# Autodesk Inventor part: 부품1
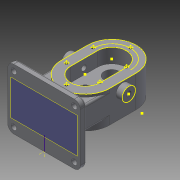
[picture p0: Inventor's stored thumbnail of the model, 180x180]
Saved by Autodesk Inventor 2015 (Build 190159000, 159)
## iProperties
Created: 2020-09
Part Number: 부품1
Material: 일반
Document SubType Name: Modeling
Designer: Main
Density: 1 g/cm^3
Appearance: 기본값
Author: Main
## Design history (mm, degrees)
sketch "스케치2"
  geometry: L1 (0, 0)-(0, -44); L2 (-40, 0)-(-40, -44); L3 (40, -44)-(40, 0); L4 (0, 0)-(0, -44); L5 (-24, 0)-(-24, -44); L6 (24, -44)-(24, 0); L7 (0, 0)-(0, -44); L8 (-31, 0)-(-31, -44); L9 (31, -44)-(31, 0); C1 r 12.5 at (0, 0); C2 r 12.5 at (0, -44); A1 r 40 centre (0, 0) between (40, 0) and (-40, 0); A2 r 40 centre (0, -44) between (-40, -44) and (40, -44); A3 r 24 centre (0, 0) between (24, 0) and (-24, 0); A4 r 24 centre (0, -44) between (-24, -44) and (24, -44); A5 r 31 centre (0, 0) between (31, 0) and (-31, 0); A6 r 31 centre (0, -44) between (-31, -44) and (31, -44); 3 further points
  constraints: 24 end point, 12 point on circle, 12 tangent, 8 centre point, 5 equal length, 3 midpoint, 2 coincident, 1 vertical
extrude "돌출1" new body sketch "스케치2" distance "d2" = 29; taper "d3" = 0 deg
extrude "돌출2" join sketch "스케치2" distance "d4" = 53; taper "d5" = 0 deg
extrude "돌출3" join sketch "스케치2" distance "d6" = 14; taper "d7" = 0 deg
sketch "스케치3"
  geometry: L1 (24, 0)-(24, -44) reference; L2 (-24, -44)-(-24, 0) reference; L3 (-40, 0)-(-40, -44) reference; L4 (40, -44)-(40, 0) reference; L5 (24, 0)-(24, -44) reference; L6 (-24, -44)-(-24, 0) reference; L7 (-40, 0)-(-40, -44) reference; L8 (40, -44)-(40, 0) reference; A1 r 24 centre (0, 0) between (24, 0) and (-24, 0) reference; A2 r 24 centre (0, -44) between (-24, -44) and (24, -44) reference; A3 r 40 centre (0, -44) between (-40, -44) and (40, -44) reference; A4 r 40 centre (0, 0) between (40, 0) and (-40, 0) reference; A5 r 31 centre (0, 0) between (31, 0) and (-31, 0) reference; A6 r 24 centre (0, 0) between (24, 0) and (-24, 0) reference; A7 r 24 centre (0, -44) between (-24, -44) and (24, -44) reference; A8 r 40 centre (0, -44) between (-40, -44) and (40, -44) reference; A9 r 40 centre (0, 0) between (40, 0) and (-40, 0) reference
  node "투영된 루프1"
node "작업 평면1"
sketch "스케치4"
  geometry: L1 (0, 53)-(-44, 53) reference; L2 (-22, 53)-(-22, 39); C1 r 11 at (-22, 39); 1 further point
  constraints: 2 end point, 1 centre point, 1 coincident, 1 midpoint, 1 vertical
extrude "돌출4" join sketch "스케치4" distance "d9" = 10; taper "d10" = 0 deg
sketch "스케치5"
  geometry: C1 r 11 at (0, 0) reference; 1 further point
hole "구멍1" diameter "d13" = 8.376; stored, may be unused: countersink angle "d17" = 90 deg, drill point angle "d19" = 118 deg; dims "d11" = 10, "d12" = 10, "d14" = 20, "d15" = 4, "d16" = 2, "d18" = 27.3
node "작업 평면2"
sketch "스케치6"
  geometry: L1 (-40, 0)-(-40, 53) reference; L2 (-40, 26.5)-(40, 26.5); L3 (40, 0)-(40, 53) reference; L4 (-60, 76.5)-(60, 76.5); L5 (60, 76.5)-(60, -23.5); L6 (60, -23.5)-(-60, -23.5); L7 (-60, -23.5)-(-60, 76.5); L8 (-60, 76.5)-(60, -23.5); L9 (60, 76.5)-(-60, -23.5); 2 further points
  constraints: 14 end point, 5 midpoint, 2 parallel, 1 horizontal, 1 perpendicular
extrude "돌출5" join sketch "스케치6" distance "d21" = 10; taper "d22" = 0 deg
fillet "모깎기1" dims "d23" = 10
sketch "스케치7"
  geometry: C1 r 4.5 at (-50, 13.5); C2 r 4.5 at (50, 13.5); C3 r 4.5 at (50, -66.5); C4 r 4.5 at (-50, -66.5); A1 r 10 centre (50, 13.5) between (60, 13.5) and (50, 23.5) reference; A2 r 10 centre (-50, 13.5) between (-50, 23.5) and (-60, 13.5) reference; A3 r 10 centre (-50, -66.5) between (-60, -66.5) and (-50, -76.5) reference; A4 r 10 centre (50, -66.5) between (50, -76.5) and (60, -66.5) reference; 1 further point
  constraints: 4 centre point, 4 coincident
extrude "돌출6" cut sketch "스케치7" distance "d24" = 10; taper "d25" = 0 deg
sketch "스케치8"
  geometry: 1 further point
sketch "스케치9"
  geometry: L1 (-112, -23.5)-(-112, 0); 1 further point
  constraints: 2 end point, 1 vertical
node "작업 평면3"
sketch "스케치10"
  geometry: L1 (0, -102)-(-40, -102); L2 (50, -102)-(-50, -102) reference; L3 (-40, -102)-(-40, -44); L4 (-40, 0)-(-40, -44) reference; L5 (0, -102)-(40, -102); L6 (40, -102)-(40, -44); A1 r 40 centre (0, -44) between (-40, -44) and (40, -44) reference; A2 r 40 centre (0, -44) between (-40, -44) and (40, -44); 1 further point
  constraints: 8 end point, 3 tangent, 2 point on circle, 2 point on line, 1 centre point, 1 collinear, 1 perpendicular
extrude "돌출7" join sketch "스케치10" distance "d27" = 37; taper "d28" = 0 deg
fillet "모깎기2" dims "d29" = 3
node "작업 평면4"
sketch "스케치11"
  geometry: C1 r 12.5 at (0, 0) reference; C2 r 8.5 at (0, 0); C3 r 14 at (0, 0); C4 r 19 at (0, 0); 1 further point
  constraints: 3 centre point, 3 coincident
extrude "돌출8" join sketch "스케치11" distance "d31" = 17; taper "d32" = 0 deg
extrude "돌출9" cut sketch "스케치11" distance "d33" = 8; taper "d34" = 0 deg
extrude "돌출10" cut sketch "스케치11" distance "d35" = 40; taper "d36" = 0 deg
sketch "스케치12"
  geometry: L1 (0, 0)-(0, -44); L2 (-31, 0)-(-31, -44); L3 (31, -44)-(31, 0); A1 r 40 centre (0, -44) between (-40, -44) and (40, -44) reference; A2 r 40 centre (0, 0) between (40, 0) and (-40, 0) reference; A3 r 31 centre (0, 0) between (31, 0) and (-31, 0); A4 r 31 centre (0, -44) between (-31, -44) and (31, -44); A5 r 31 centre (0, 0) between (31, 0) and (-31, 0) reference; 2 further points
  constraints: 8 end point, 4 point on circle, 4 tangent, 2 centre point, 1 midpoint, 1 parallel, 1 vertical
sketch "스케치13"
  geometry: L1 (24, 0)-(24, -44) reference; L2 (-24, -44)-(-24, 0) reference; L3 (-40, 0)-(-40, -44) reference; L4 (40, -44)-(40, 0) reference; A1 r 24 centre (0, 0) between (24, 0) and (-24, 0) reference; A2 r 24 centre (0, -44) between (-24, -44) and (24, -44) reference; A3 r 40 centre (0, -44) between (-40, -44) and (40, -44) reference; A4 r 40 centre (0, 0) between (40, 0) and (-40, 0) reference
sketch "스케치14"
  geometry: L1 (0, -75.027)-(0, 30.955); L2 (-31.226, -44)-(24, -44); L3 (-50, -17.812)-(-24, -17.812) reference; L4 (-31.226, 0)-(24, 0)
  constraints: 6 end point, 2 parallel, 1 vertical
node "작업점1"
node "작업점2"
node "작업점3"
node "작업점4"
node "작업점5"
node "작업점6"
hole "구멍2" diameter "d39" = 4.134; stored, may be unused: countersink angle "d43" = 90 deg, drill point angle "d45" = 118 deg; dims "d37" = 10, "d38" = 10, "d40" = 10, "d41" = 4, "d42" = 2, "d44" = 12
hole "구멍3" sketch "스케치14" diameter "d46" = 4.134; stored, may be unused: countersink angle "d50" = 90 deg, drill point angle "d52" = 118 deg; dims "d47" = 10, "d48" = 4, "d49" = 2, "d51" = 12
hole "구멍4" sketch "스케치12" diameter "d53" = 4.134; stored, may be unused: countersink angle "d57" = 90 deg, drill point angle "d59" = 118 deg; dims "d54" = 10, "d55" = 4, "d56" = 2, "d58" = 12
hole "구멍5" diameter "d62" = 4.134; stored, may be unused: countersink angle "d66" = 90 deg, drill point angle "d68" = 118 deg; dims "d60" = 10, "d61" = 10, "d63" = 10, "d64" = 4, "d65" = 2, "d67" = 12
node "솔리드1"
mirror "대칭1"
other parameters: "d20" = -112, "d26" = 11.5, "d30" = -17
